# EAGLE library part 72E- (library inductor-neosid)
FILTER dual helix bandpass filter, type E
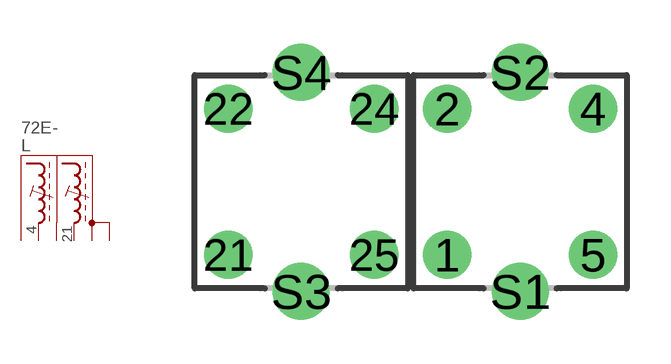
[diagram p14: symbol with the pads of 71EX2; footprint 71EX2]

Designator prefix L

## 72E-4-21 (OC_FARNELL: unknown; OC_NEWARK: unknown)  [71EX2]
4  IN  pas
21  OUT  pas
S1  S1  pas
S2  S2  pas
S3  S3  pas
S4  S4  pas

## 72E-4-22 (OC_FARNELL: unknown; OC_NEWARK: unknown)  [71EX2]
4  IN  pas
22  OUT  pas
S1  S1  pas
S2  S2  pas
S3  S3  pas
S4  S4  pas

## 72E-5-22 (OC_FARNELL: unknown; OC_NEWARK: unknown)  [71EX2]
5  IN  pas
22  OUT  pas
S1  S1  pas
S2  S2  pas
S3  S3  pas
S4  S4  pas

## 72E-4-24 (OC_FARNELL: unknown; OC_NEWARK: unknown)  [71EX2]
4  IN  pas
24  OUT  pas
S1  S1  pas
S2  S2  pas
S3  S3  pas
S4  S4  pas

## 72E-1-24 (OC_FARNELL: unknown; OC_NEWARK: unknown)  [71EX2]
1  IN  pas
24  OUT  pas
S1  S1  pas
S2  S2  pas
S3  S3  pas
S4  S4  pas

## 72E-1-22 (OC_FARNELL: unknown; OC_NEWARK: unknown)  [71EX2]
1  IN  pas
22  OUT  pas
S1  S1  pas
S2  S2  pas
S3  S3  pas
S4  S4  pas

## 72E-2-22 (OC_FARNELL: unknown; OC_NEWARK: unknown)  [71EX2]
2  IN  pas
22  OUT  pas
S1  S1  pas
S2  S2  pas
S3  S3  pas
S4  S4  pas

## 72E-1-21 (OC_FARNELL: unknown; OC_NEWARK: unknown)  [71EX2]
1  IN  pas
21  OUT  pas
S1  S1  pas
S2  S2  pas
S3  S3  pas
S4  S4  pas

## Footprint 71EX2 (pad centres in mm)
DUAL RF COIL ASSEMBLY 1 winding, 4 pads, grid 2.5 mm
drill 1.1 round: 1 1.25,-2.5; 2 1.25,2.5; 4 6.25,2.5; 5 6.25,-2.5; 21 -6.25,-2.5; 22 -6.25,2.5; 24 -1.25,2.5; 25 -1.25,-2.5
drill 1.3 round: S1 3.75,-3.75; S2 3.75,3.75; S3 -3.75,-3.75; S4 -3.75,3.75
